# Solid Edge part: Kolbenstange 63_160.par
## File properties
Username: ahadarics
Dokumentum tartalom típus: 0
Author: ahadarics
Last saved by: ahadarics
Revision: 84
Sűrűség: 0,000 kg/m^3
Pontosság: 0,990
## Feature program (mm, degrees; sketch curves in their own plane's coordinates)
base feature "unnamed BaseFeature 1"
thread "unnamed Thread 1"
chamfer "Letörés_1"  SetBackValue2 = 20 deg
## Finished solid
Body 1: solid body, 20 faces, 31 edges, 14 vertices.
  Faces by surface: plane 8, cylinder 5, torus 4, cone 3
  Edges by curve: circle 16, line 9, curve on surface 4, ellipse 2
Bounding box of the edges (mm; curved faces can reach further): 63.000 x 63.000 x 316.500, from (-31.5, -31.5, -70.75) to (31.5, 31.5, 245.75).
Cylindrical faces by radius (mm): R6.75 x1, R8 x1, R9.75 x1, R10 x1, R31.5 x1
Conical faces (half-angle, radius in mm at the cone's reference point): 20 deg R8 x1, 30 deg R9.875 x1, 60 deg R7.375 x1
Toroidal faces (ring radius, tube radius in mm): R7.15 r0.4 x2, R8.55 r1.2 x2
Planar faces by outward normal: +x 1, +z 3, -x 1, -z 1, oblique 2
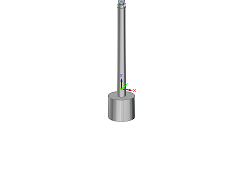
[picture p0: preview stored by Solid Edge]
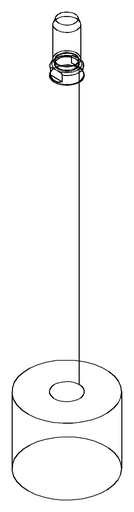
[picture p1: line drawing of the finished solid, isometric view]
